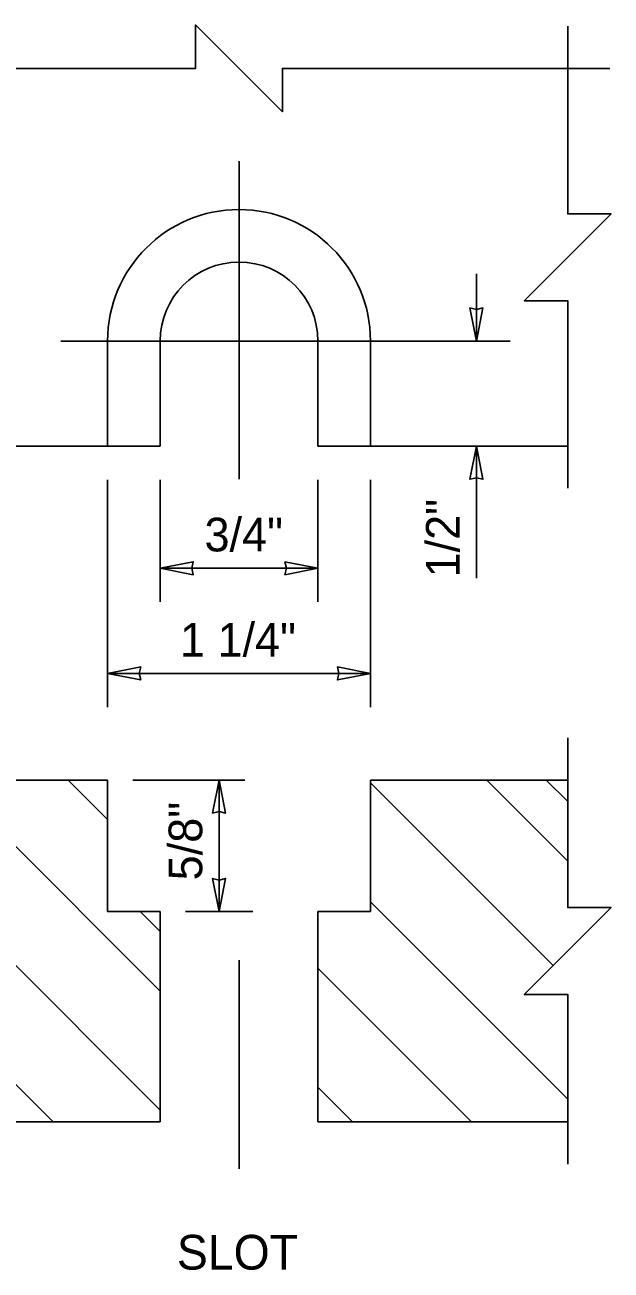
# Model space of a CAD drawing. Extents: x 99862 to 103151, y 100000 to 102076.
# Drawn here: x 102211 to 102490, y 101016 to 101608 of the extents above; entities that cross this region are included whole.
import ezdxf

# ---------------------------------------------------------------- set-up
doc = ezdxf.new("R2010")
doc.units = 0
for name, color, linetype in [('Level 1', 7, 'Continuous'), ('Level 15', 7, 'Continuous'), ('Level 17', 7, 'Continuous'), ('Level 2', 7, 'Continuous'), ('Level 20', 7, 'Continuous')]:
    doc.layers.add(name, color=color, linetype=linetype)

msp = doc.modelspace()

# ---------------------------------------------------------------- linework, layer by layer
at = {"layer": 'Level 15'}
for p, q in [((102312.72, 101391.81), (102312.72, 101542.9)), ((102425.61, 101489.42), (102425.61, 101457.42)), ((102228, 101457.42), (102441.61, 101457.42)), ((102425.61, 101407.42), (102425.61, 101344.64)), ((102250.22, 101391.42), (102250.22, 101283.42)), ((102275.22, 101391.42), (102275.22, 101333.42)), ((102350.22, 101391.42), (102350.22, 101333.42)), ((102375.22, 101391.42), (102375.22, 101283.42)), ((102275.22, 101349.42), (102350.22, 101349.42)), ((102250.22, 101299.42), (102375.22, 101299.42)), ((102262.22, 101248.75), (102315.5, 101248.75)), ((102303.22, 101186.25), (102303.22, 101248.75)), ((102287.22, 101186.25), (102319.22, 101186.25)), ((102312.72, 101063.91), (102312.72, 101163.19))]:
    msp.add_line(p, q, dxfattribs=at)
for points in [[(102136.46, 101587.02), (102292.07, 101587.02), (102292.07, 101607.66), (102333.37, 101566.37), (102333.37, 101587.02), (102488.99, 101587.02)], [(102468.99, 101607.02), (102468.99, 101517.86), (102489.64, 101517.86), (102448.34, 101476.57), (102468.99, 101476.57), (102468.99, 101387.42)], [(102468.99, 101268.75), (102468.99, 101188.14), (102489.64, 101188.14), (102448.34, 101146.85), (102468.99, 101146.85), (102468.99, 101066.25)]]:
    msp.add_lwpolyline(points, dxfattribs=at)
for points in [[(102425.61, 101457.42), (102422.52, 101473.14), (102425.61, 101472.41), (102428.69, 101473.14)], [(102425.61, 101407.42), (102422.52, 101391.69), (102425.61, 101392.42), (102428.69, 101391.69)], [(102275.22, 101349.42), (102290.95, 101346.33), (102290.22, 101349.42), (102290.95, 101352.5)], [(102350.22, 101349.42), (102334.5, 101346.33), (102335.23, 101349.42), (102334.5, 101352.5)], [(102250.22, 101299.42), (102265.95, 101296.33), (102265.22, 101299.42), (102265.95, 101302.5)], [(102375.22, 101299.42), (102359.5, 101296.33), (102360.23, 101299.42), (102359.5, 101302.5)], [(102303.22, 101248.75), (102300.14, 101233.02), (102303.22, 101233.75), (102306.31, 101233.02)], [(102303.22, 101186.25), (102300.14, 101201.97), (102303.22, 101201.24), (102306.31, 101201.97)]]:
    msp.add_lwpolyline(points, close=True, dxfattribs=at)
at = {"layer": 'Level 17'}
for p, q in [((102275.22, 101148.48), (102174.96, 101248.75)), ((102250.22, 101230.05), (102231.52, 101248.75)), ((102462.07, 101160.58), (102375.22, 101247.43)), ((102468.99, 101210.23), (102430.48, 101248.75)), ((102468.99, 101238.52), (102458.76, 101248.75)), ((102275.22, 101091.91), (102156.46, 101210.68)), ((102275.22, 101176.76), (102265.74, 101186.25)), ((102468.99, 101097.1), (102375.22, 101190.86)), ((102224.32, 101086.25), (102149.76, 101160.8)), ((102423.27, 101086.25), (102350.22, 101159.3)), ((102366.7, 101086.25), (102350.22, 101102.73))]:
    msp.add_line(p, q, dxfattribs=at)
at = {"layer": 'Level 2'}
for p, q in [((102250.22, 101457.42), (102250.22, 101407.42)), ((102275.22, 101457.42), (102275.22, 101407.42)), ((102350.22, 101457.42), (102350.22, 101407.42)), ((102375.22, 101457.42), (102375.22, 101407.42)), ((102275.22, 101407.42), (102156.46, 101407.42)), ((102350.22, 101407.42), (102468.99, 101407.42)), ((102156.46, 101248.75), (102250.22, 101248.75)), ((102250.22, 101248.75), (102250.22, 101186.25)), ((102375.22, 101248.75), (102375.22, 101186.25)), ((102468.99, 101248.75), (102375.22, 101248.75)), ((102250.22, 101186.25), (102275.22, 101186.25)), ((102275.22, 101186.25), (102275.22, 101086.25)), ((102375.22, 101186.25), (102350.22, 101186.25)), ((102350.22, 101186.25), (102350.22, 101086.25)), ((102156.46, 101086.25), (102275.22, 101086.25)), ((102468.99, 101086.25), (102350.22, 101086.25))]:
    msp.add_line(p, q, dxfattribs=at)
for radius in [62.5, 37.5]:
    msp.add_arc((102312.72, 101457.42), radius, 360, 180, dxfattribs=at)

# ---------------------------------------------------------------- texts
at = {"layer": 'Level 1'}
msp.add_text('SLOT', height=16.5, dxfattribs=at).set_placement((102283.15, 101016.07))
at = {"layer": 'Level 20'}
for s, p in [('1/2"', (102417.61, 101345.04)), ('5/8"', (102295.22, 101201.07))]:
    msp.add_text(s, height=16, rotation=90, dxfattribs=at).set_placement(p)
for s, p in [('3/4"', (102296.3, 101357.42)), ('1 1/4"', (102284.63, 101307.42))]:
    msp.add_text(s, height=16, dxfattribs=at).set_placement(p)

doc.saveas('drawing.dxf')
